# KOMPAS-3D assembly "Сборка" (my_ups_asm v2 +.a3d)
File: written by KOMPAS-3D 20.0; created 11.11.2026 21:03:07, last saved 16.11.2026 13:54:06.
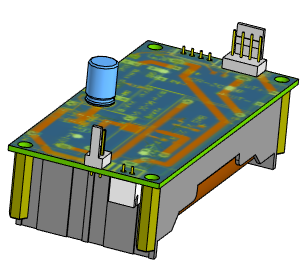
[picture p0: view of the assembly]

Document properties: Полное имя файла: D:\RicWork\Project-EPS32\box_compas\ups 18650\my_ups_asm v2 +.a3d

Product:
- Part/product: Сборка
    Масса: 0.445153
  - Component [detail]: Деталь  | qty 2  | Масса: 0.000922909; source file: ..\разъемы\B2B-XH-A.m3d
  - Component [detail]: Деталь  | qty 2  | Масса: 0.00142227; source file: ..\разъемы\B4B-XH-A.m3d
  - Component [detail]: Деталь  | Масса: 0.00202132; source file: ..\разъемы\WF-4 (DS1070-4 M).m3d
  - Component [detail]: Деталь  | Масса: 0.000929543; source file: ..\разъемы\WF-2 (DS1070-2 M).m3d
  - Component [detail]: Деталь  | Масса: 0.00447634; source file: ..\прочее\1000mkf 8x11.5 p3.5 (JRB1A102M03500800115000B).m3d
  - Component [detail]: Деталь  | qty 2  | Масса: 0.12809; source file: 18650 acc.m3d
  - Component [detail]: Деталь  | Масса: 0.123603; source file: battery 18650 case x2.m3d
  - Component [detail]: Деталь  | Масса: 0.0452623; source file: my_ups v2.m3d
  - Component [detail]: Деталь  | qty 4  | Масса: 0.0019975; source file: ..\прочее\PCHSS-19.m3d

Referenced files in D:\RicWork\Project-EPS32\box_compas\ups 18650\: my_ups v2.m3d, battery 18650 case x2.m3d, 18650 acc.m3d
Referenced files in D:\RicWork\Project-EPS32\box_compas\прочее\: PCHSS-19.m3d, 1000mkf 8x11.5 p3.5 (JRB1A102M03500800115000B).m3d
Referenced files in D:\RicWork\Project-EPS32\box_compas\разъемы\: WF-2 (DS1070-2 M).m3d, WF-4 (DS1070-4 M).m3d, B4B-XH-A.m3d, B2B-XH-A.m3d
Referenced files in D:\myProjects\Progect_esp32\box_compas\ups 18650\: 18650 acc.m3d
Referenced files in D:\myProjects\Progect_esp32\box_compas\прочее\: PCHSS-19.m3d
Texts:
  Деталь (1)
  Деталь (2)
  Деталь (3)
  Деталь (4)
